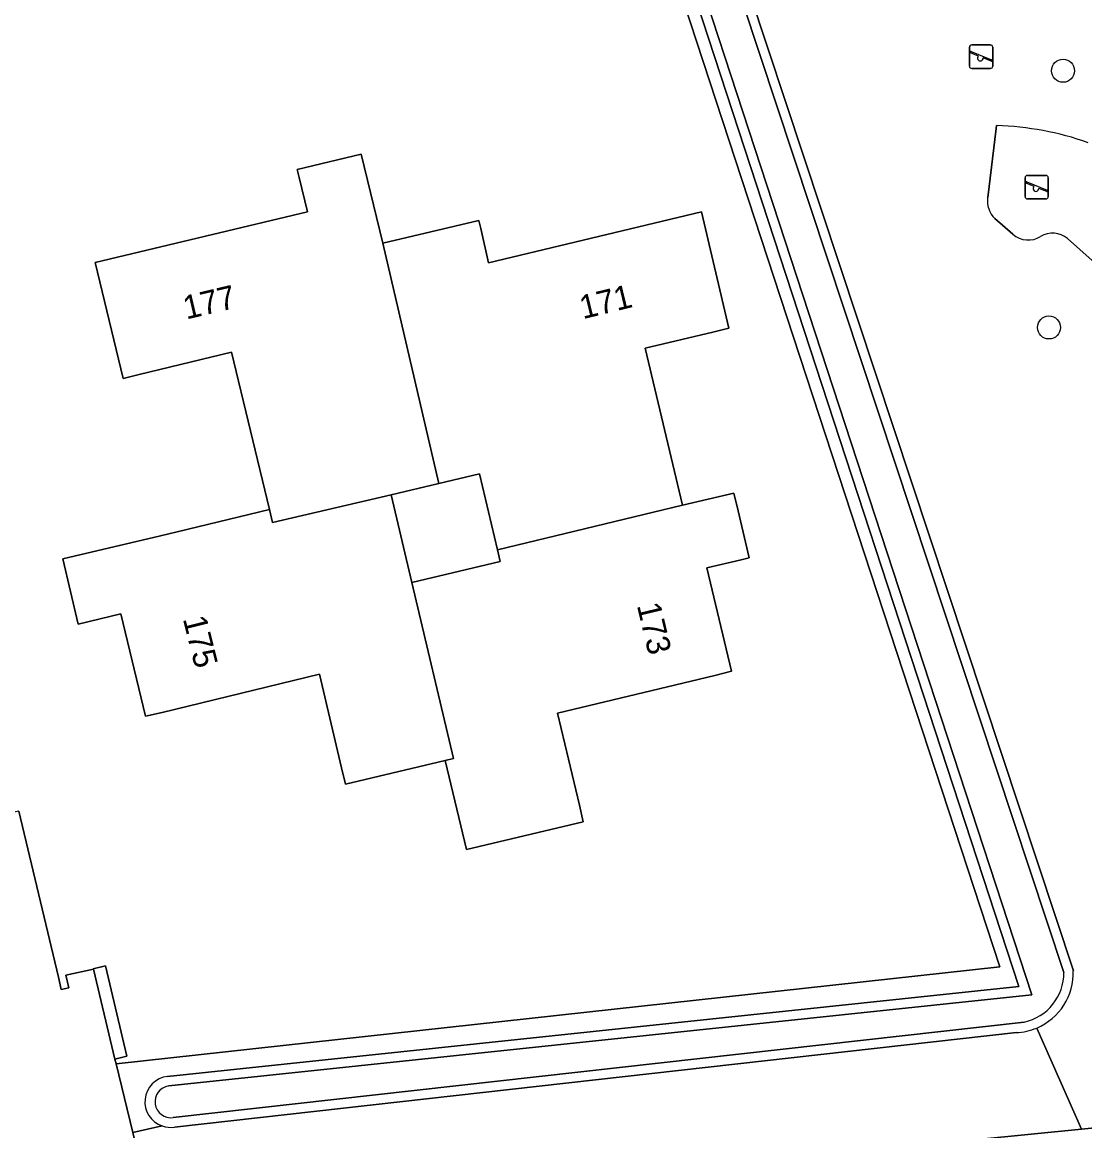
# Model space of a CAD drawing. Extents: x 156661 to 157576, y 383570 to 384425.
# Drawn here: x 156959.72 to 157004.92, y 383936.19 to 383983.33 of the extents above; entities that cross this region are included whole.
import ezdxf

# ---------------------------------------------------------------- set-up
doc = ezdxf.new("R2010")
doc.units = 0
for name, color, linetype in [('IMGEO_Boom', 7, 'Continuous'), ('IMGEO_Erf', 7, 'Continuous'), ('IMGEO_Groenvoorziening', 7, 'Continuous'), ('IMGEO_Haag', 7, 'Continuous'), ('IMGEO_Hek', 7, 'Continuous'), ('IMGEO_Muur', 7, 'Continuous'), ('IMGEO_Oever', 7, 'Continuous'), ('IMGEO_Pand', 7, 'Continuous'), ('IMGEO_Pand_nummerreeks', 7, 'Continuous'), ('IMGEO_Rijbaan_lokaal_open', 7, 'Continuous'), ('IMGEO_Speelvoorziening', 7, 'Continuous'), ('IMGEO_Terreindeel_zand', 7, 'Continuous'), ('IMGEO_Waterloop', 7, 'Continuous')]:
    doc.layers.add(name, color=color, linetype=linetype)

msp = doc.modelspace()

# ---------------------------------------------------------------- linework, layer by layer
at = {"layer": 'IMGEO_Boom'}
for centre in [(157003.99, 383981.261), (157003.391, 383970.345)]:
    msp.add_circle(centre, 0.489, dxfattribs=at)
at = {"layer": 'IMGEO_Erf'}
msp.add_lwpolyline([(156959.573, 383949.776), (156961.258, 383942.72), (156961.383, 383942.196), (156961.704, 383942.271), (156961.579, 383942.807), (156962.748, 383943.053), (156962.741, 383943.079), (156963.264, 383943.206), (156964.173, 383939.363), (156963.662, 383939.235), (156963.71, 383939.037), (157001.305, 383943.16), (156984.848, 383993.384), (156971.911, 384032.865), (156863.465, 384006.689)], dxfattribs=at)
for points in [[(156962.825, 383973.112), (156971.852, 383975.263), (156971.504, 383976.722), (156971.415, 383977.062), (156974.137, 383977.717), (156975.06, 383973.932), (156979.145, 383974.9), (156979.223, 383974.559), (156979.558, 383973.088), (156988.618, 383975.257), (156989.777, 383970.317), (156989.088, 383970.151), (156986.213, 383969.465), (156987.808, 383962.783), (156989.993, 383963.295), (156990.169, 383962.548), (156990.641, 383960.543), (156990.301, 383960.462), (156988.84, 383960.119), (156989.886, 383955.727), (156989.184, 383955.552), (156982.49, 383953.946), (156983.418, 383950.037), (156983.576, 383949.323), (156978.611, 383948.146), (156977.705, 383951.93), (156973.468, 383950.93), (156973.306, 383951.616), (156972.366, 383955.602), (156965.671, 383953.972), (156964.957, 383953.811), (156963.92, 383958.163), (156962.099, 383957.733), (156961.445, 383960.502), (156965.598, 383961.482), (156966.308, 383961.654), (156970.235, 383962.605), (156968.628, 383969.298), (156964.699, 383968.344), (156964.014, 383968.177)], [(156980.055, 383960.388), (156979.936, 383960.895), (156979.175, 383964.117), (156977.442, 383963.708), (156975.409, 383963.228), (156976.289, 383959.499)]]:
    msp.add_lwpolyline(points, close=True, dxfattribs=at)
at = {"layer": 'IMGEO_Groenvoorziening'}
for points in [[(156965.9, 383938.498), (157002.117, 383942.318), (156972.167, 384033.813), (156964.844, 384031.779), (156863.418, 384007.321)], [(156974.445, 384033.505), (156979.934, 384016.935), (157004.429, 383942.995)], [(156953.099, 383937.896), (156882.007, 383929.988), (156863.465, 384006.689), (156971.911, 384032.865), (156984.848, 383993.384), (157001.305, 383943.16), (156963.71, 383939.037), (156964.423, 383936.119), (156965.671, 383936.392)], [(157000.785, 383975.878), (157001.148, 383978.803), (157001.163, 383978.927)], [(157001.857, 383974.31), (157001.093, 383974.975)], [(157006.403, 383972.141), (157004.174, 383974.126)], [(157002.005, 383940.362), (156966.194, 383936.347)], [(157004.772, 383936.263), (157002.87, 383940.558)], [(157002.87, 383940.558), (157004.772, 383936.263), (157008.609, 383936.644), (157008.658, 383936.146), (157008.707, 383935.648), (157008.85, 383933.899), (157012.523, 383934.255), (157027.632, 383935.51), (157049.754, 383937.359)], [(156965.671, 383936.392), (156964.423, 383936.119), (156965.744, 383930.718), (156966.535, 383929.792), (157008.85, 383933.899), (157008.707, 383935.648), (156966.501, 383931.453), (156966.452, 383931.95), (156966.402, 383932.448), (157004.772, 383936.263)]]:
    msp.add_lwpolyline(points, dxfattribs=at)
msp.add_lwpolyline([(157008.707, 383935.648), (157008.658, 383936.146), (157008.609, 383936.644), (157004.772, 383936.263), (156966.402, 383932.448), (156966.452, 383931.95), (156966.501, 383931.453)], close=True, dxfattribs=at)
for centre, radius, start, end in [((157000.806, 383966.164), 12.768, 70.5184, 88.3967), ((157001.821, 383975.727), 1.047, 171.7222, 225.9453), ((157002.51, 383975.053), 0.989, 228.6942, 302.3082), ((157003.542, 383973.368), 0.987, 50.1899, 120.6422), ((157001.886, 383942.904), 2.544, 292.7454, 2.0388), ((157001.884, 383942.904), 2.545, 272.7309, 292.8032), ((156966.024, 383937.419), 1.086, 96.5436, 251.0448), ((156966.025, 383937.44), 1.106, 251.3526, 278.8119)]:
    msp.add_arc(centre, radius, start, end, dxfattribs=at)
at = {"layer": 'IMGEO_Haag'}
msp.add_lwpolyline([(157008.707, 383935.648), (157008.658, 383936.146), (157008.609, 383936.644), (157004.772, 383936.263), (156966.402, 383932.448), (156966.452, 383931.95), (156966.501, 383931.453)], close=True, dxfattribs=at)
at = {"layer": 'IMGEO_Hek'}
for points in [[(156953.099, 383937.896), (156882.007, 383929.988), (156863.465, 384006.689), (156971.911, 384032.865), (156984.848, 383993.384), (157001.305, 383943.16)], [(157001.305, 383943.16), (156963.71, 383939.037)]]:
    msp.add_lwpolyline(points, dxfattribs=at)
at = {"layer": 'IMGEO_Muur'}
msp.add_lwpolyline([(156964.173, 383939.363), (156963.264, 383943.206), (156962.741, 383943.079), (156962.748, 383943.053), (156963.662, 383939.235)], close=True, dxfattribs=at)
for points in [[(156961.383, 383942.196), (156961.258, 383942.72)], [(156961.704, 383942.271), (156961.383, 383942.196)]]:
    msp.add_lwpolyline(points, dxfattribs=at)
at = {"layer": 'IMGEO_Oever'}
for points in [[(156965.949, 383938.095), (157002.659, 383941.967), (156972.432, 384034.308), (156964.742, 384032.172), (156863.303, 384007.711)], [(156863.418, 384007.321), (156964.844, 384031.779), (156972.167, 384033.813), (157002.117, 383942.318), (156965.9, 383938.498)], [(156973.994, 384033.587), (156979.549, 384016.807), (156979.576, 384016.724), (157004.025, 383942.925)], [(157004.429, 383942.995), (156979.934, 384016.935)], [(157002.336, 383940.813), (156966.143, 383936.75)], [(156966.194, 383936.347), (157002.005, 383940.362)]]:
    msp.add_lwpolyline(points, dxfattribs=at)
for centre, radius, start, end in [((157001.885, 383942.905), 2.14, 282.1674, 0.5328), ((157001.886, 383942.904), 2.544, 292.7454, 2.0388), ((157001.884, 383942.904), 2.545, 272.7309, 292.8032), ((156966.024, 383937.419), 1.086, 96.5436, 251.0448), ((156966.047, 383937.423), 0.679, 98.2554, 278.1599), ((156966.025, 383937.44), 1.106, 251.3526, 278.8119)]:
    msp.add_arc(centre, radius, start, end, dxfattribs=at)
at = {"layer": 'IMGEO_Pand'}
for points in [[(156975.409, 383963.228), (156977.442, 383963.708), (156975.06, 383973.932), (156974.137, 383977.717), (156971.415, 383977.062), (156971.504, 383976.722), (156971.852, 383975.263), (156962.825, 383973.112), (156964.014, 383968.177), (156964.699, 383968.344), (156968.628, 383969.298), (156970.235, 383962.605), (156970.369, 383962.049)], [(156979.936, 383960.895), (156987.808, 383962.783), (156986.213, 383969.465), (156989.088, 383970.151), (156989.777, 383970.317), (156988.618, 383975.257), (156979.558, 383973.088), (156979.223, 383974.559), (156979.145, 383974.9), (156975.06, 383973.932), (156977.442, 383963.708), (156979.175, 383964.117)], [(156975.409, 383963.228), (156970.369, 383962.049), (156970.235, 383962.605), (156966.308, 383961.654), (156965.598, 383961.482), (156961.445, 383960.502), (156962.099, 383957.733), (156963.92, 383958.163), (156964.957, 383953.811), (156965.671, 383953.972), (156972.366, 383955.602), (156973.306, 383951.616), (156973.468, 383950.93), (156977.705, 383951.93), (156978.063, 383952.018), (156976.289, 383959.499)], [(156979.936, 383960.895), (156980.055, 383960.388), (156976.289, 383959.499), (156978.063, 383952.018), (156977.705, 383951.93), (156978.611, 383948.146), (156983.576, 383949.323), (156983.418, 383950.037), (156982.49, 383953.946), (156989.184, 383955.552), (156989.886, 383955.727), (156988.84, 383960.119), (156990.301, 383960.462), (156990.641, 383960.543), (156990.169, 383962.548), (156989.993, 383963.295), (156987.808, 383962.783)]]:
    msp.add_lwpolyline(points, close=True, dxfattribs=at)
at = {"layer": 'IMGEO_Rijbaan_lokaal_open'}
msp.add_lwpolyline([(156963.71, 383939.037), (156963.662, 383939.235), (156962.748, 383943.053), (156961.579, 383942.807), (156961.704, 383942.271), (156961.383, 383942.196), (156961.258, 383942.72), (156959.573, 383949.776), (156954.882, 383948.869), (156956.564, 383941.597), (156956.615, 383941.611), (156956.745, 383941.083), (156957.783, 383936.781), (156959.604, 383929.198), (156958.753, 383927.533), (156957.067, 383924.307), (156970.285, 383925.601), (156967.792, 383928.413), (156966.535, 383929.792), (156965.744, 383930.718), (156964.423, 383936.119)], close=True, dxfattribs=at)
at = {"layer": 'IMGEO_Speelvoorziening'}
for p, q in [((157000.109, 383982.358), (157000.899, 383982.358)), ((157000.899, 383982.358), (157000.109, 383982.358)), ((157000.009, 383981.458), (157000.009, 383982.258)), ((157000.009, 383982.258), (157000.009, 383981.458)), ((157000.392, 383981.886), (157000.053, 383982.023)), ((157000.078, 383982.083), (157000.954, 383981.73)), ((157000.999, 383982.258), (157000.999, 383981.458)), ((157000.999, 383981.458), (157000.999, 383982.258)), ((157000.899, 383981.358), (157000.109, 383981.358)), ((157000.109, 383981.358), (157000.899, 383981.358)), ((157000.93, 383981.67), (157000.59, 383981.807)), ((157002.375, 383975.911), (157002.375, 383976.711)), ((157002.375, 383976.711), (157002.375, 383975.911)), ((157002.475, 383976.811), (157003.265, 383976.811)), ((157003.265, 383976.811), (157002.475, 383976.811)), ((157003.365, 383976.711), (157003.365, 383975.911)), ((157003.365, 383975.911), (157003.365, 383976.711)), ((157002.758, 383976.339), (157002.419, 383976.476)), ((157002.444, 383976.536), (157003.32, 383976.183)), ((157003.296, 383976.123), (157002.956, 383976.26)), ((157003.265, 383975.811), (157002.475, 383975.811)), ((157002.475, 383975.811), (157003.265, 383975.811))]:
    msp.add_line(p, q, dxfattribs=at)
for centre, radius, start, end in [((157000.109, 383982.258), 0.1, 90, 180), ((157000.109, 383982.258), 0.1, 90, 180), ((157000.899, 383982.258), 0.1, 0, 90), ((157000.899, 383982.258), 0.1, 360, 90), ((157000.066, 383982.053), 0.0327, 68.078, 248.078), ((157000.471, 383981.796), 0.12, 130.9928, 5.1632), ((157000.109, 383981.458), 0.1, 180, 270), ((157000.109, 383981.458), 0.1, 180, 270), ((157000.899, 383981.458), 0.1, 270, 0), ((157000.899, 383981.458), 0.1, 270, 0), ((157000.942, 383981.7), 0.0327, 248.078, 68.078), ((157002.475, 383976.711), 0.1, 90, 180), ((157002.475, 383976.711), 0.1, 90, 180), ((157003.265, 383976.711), 0.1, 0, 90), ((157003.265, 383976.711), 0.1, 360, 90), ((157002.432, 383976.506), 0.0327, 68.078, 248.078), ((157002.837, 383976.249), 0.12, 130.9928, 5.1632), ((157003.308, 383976.153), 0.0327, 248.078, 68.078), ((157002.475, 383975.911), 0.1, 180, 270), ((157002.475, 383975.911), 0.1, 180, 270), ((157003.265, 383975.911), 0.1, 270, 0), ((157003.265, 383975.911), 0.1, 270, 0)]:
    msp.add_arc(centre, radius, start, end, dxfattribs=at)
at = {"layer": 'IMGEO_Terreindeel_zand'}
for points in [[(157001.163, 383978.927), (157001.148, 383978.803), (157000.785, 383975.878)], [(157001.093, 383974.975), (157001.857, 383974.31)], [(157004.174, 383974.126), (157006.403, 383972.141)]]:
    msp.add_lwpolyline(points, dxfattribs=at)
for centre, radius, start, end in [((157000.806, 383966.164), 12.768, 70.5184, 88.3967), ((157001.821, 383975.727), 1.047, 171.7222, 225.9453), ((157002.51, 383975.053), 0.989, 228.6942, 302.3082), ((157003.542, 383973.368), 0.987, 50.1899, 120.6422)]:
    msp.add_arc(centre, radius, start, end, dxfattribs=at)
at = {"layer": 'IMGEO_Waterloop'}
for points in [[(156863.303, 384007.711), (156964.742, 384032.172), (156972.432, 384034.308), (157002.659, 383941.967), (156965.949, 383938.095)], [(157004.025, 383942.925), (156979.576, 384016.724), (156979.549, 384016.807), (156973.994, 384033.587)], [(156966.143, 383936.75), (157002.336, 383940.813)]]:
    msp.add_lwpolyline(points, dxfattribs=at)
for centre, radius, start, end in [((157001.885, 383942.905), 2.14, 282.1674, 0.5328), ((156966.047, 383937.423), 0.679, 98.2554, 278.1599)]:
    msp.add_arc(centre, radius, start, end, dxfattribs=at)

# ---------------------------------------------------------------- texts
at = {"layer": 'IMGEO_Pand_nummerreeks'}
for s, rotation, p in [('177', 13.2084, (156966.698, 383970.681)), ('171', 13.6762, (156983.569, 383970.695)), ('173', 283.3877, (156985.86, 383958.532)), ('175', 284.0312, (156966.55, 383957.959))]:
    msp.add_text(s, height=1, rotation=rotation, dxfattribs=at).set_placement(p)

doc.saveas('drawing.dxf')
